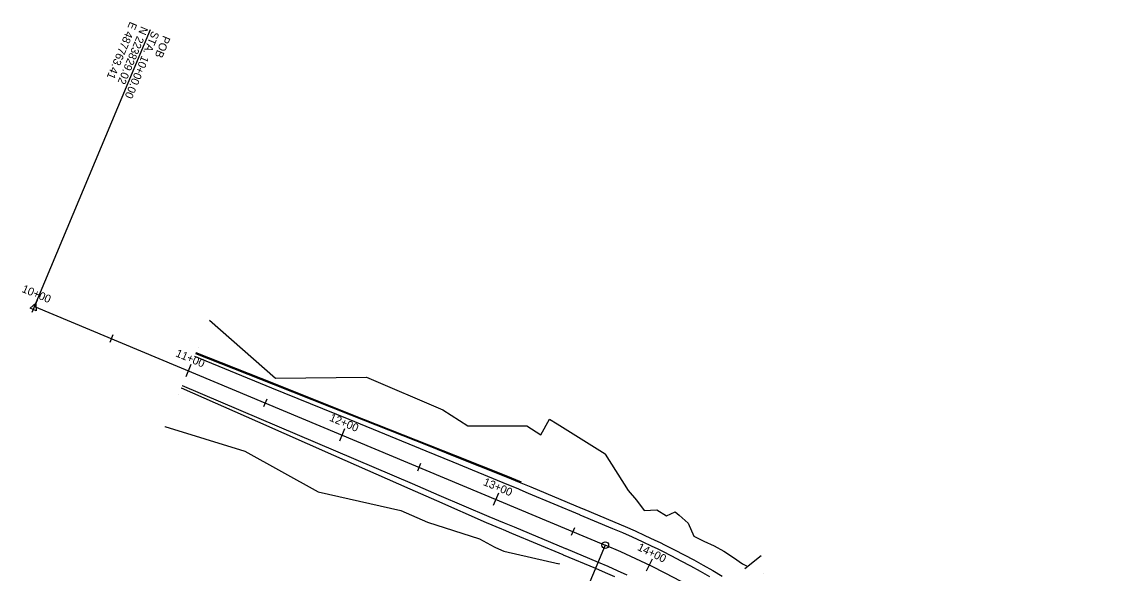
# Model space of a CAD drawing. Extents: x 487756 to 488722, y 222467 to 224000.
# Drawn here: x 487756 to 488413, y 223669 to 224000 of the extents above; entities that cross this region are included whole.
import ezdxf

# ---------------------------------------------------------------- set-up
doc = ezdxf.new("R2010")
doc.units = 0
for name, color, linetype in [('HM-SMOD-BRK LINE', 7, 'Continuous'), ('HR-FEAT-BCPC', 7, 'Continuous'), ('HR-FEAT-CUT', 7, 'Continuous'), ('HR-FEAT-EOR', 7, 'Continuous'), ('HR-FEAT-FILL', 7, 'Continuous'), ('HR-GMSC-HOR_VER ALN', 7, 'Continuous'), ('HR-GMSC-PCPT SYMB', 7, 'Continuous'), ('HR-GPLN-CL STA', 7, 'Continuous'), ('HR-GPLN-CL TICKS', 7, 'Continuous'), ('HR-GPLN-PCPT LDR', 7, 'Continuous'), ('HR-GPLN-PCPT TXT', 7, 'Continuous'), ('HR-GPLN-PI SYM', 7, 'Continuous'), ('SV_MISC_MISC_TOPO', 7, 'Continuous')]:
    doc.layers.add(name, color=color, linetype=linetype)

msp = doc.modelspace()

# ---------------------------------------------------------------- linework, layer by layer
at = {"layer": 'HM-SMOD-BRK LINE'}
for points in [[(487859.32, 223799.16), (487905.59, 223780.2), (487951.85, 223761.24), (487998.12, 223742.28), (488014.26, 223735.66), (488044.39, 223723.31), (488053.61, 223719.45), (488054.53, 223719.07), (488059.53, 223716.97), (488090.34, 223704.08), (488090.51, 223704.01), (488110.01, 223695.84), (488115.99, 223693.3), (488121.93, 223690.67), (488127.84, 223687.97), (488133.72, 223685.2), (488136.87, 223683.67), (488139.57, 223682.35), (488145.37, 223679.43), (488151.14, 223676.43), (488156.87, 223673.36), (488162.56, 223670.22), (488168.21, 223667)], [(487851.94, 223781.54), (487897.93, 223761.91), (487943.92, 223742.28), (487989.9, 223722.65), (488005.94, 223715.81), (488035.89, 223703.02), (488045.11, 223699.16), (488046.04, 223698.77), (488051.03, 223696.68), (488081.84, 223683.79), (488082.01, 223683.71), (488101.51, 223675.55), (488107.23, 223673.11), (488112.92, 223670.6), (488118.58, 223668.02)]]:
    msp.add_lwpolyline(points, dxfattribs=at)
at = {"layer": 'HR-FEAT-BCPC'}
msp.add_lwpolyline([(487860.2, 223801.27), (487906.69, 223782.84), (487953.18, 223764.41), (487999.67, 223745.97), (488015.88, 223739.55), (488046.16, 223727.54), (488055.38, 223723.68)], dxfattribs=at)
at = {"layer": 'HR-FEAT-CUT'}
msp.add_lwpolyline([(487868.36, 223820.76), (487908.02, 223786.02), (487962.45, 223786.56), (488008.4, 223766.85), (488023.34, 223757.35), (488058.62, 223757.31), (488067.17, 223751.84), (488072.27, 223761.43), (488076.9, 223758.46), (488105.58, 223740.49), (488105.69, 223740.27), (488119.55, 223718.64), (488124.43, 223712.77), (488129.07, 223706.58), (488136.66, 223706.96), (488142.41, 223703.3), (488147.68, 223705.81), (488150.13, 223703.67), (488155.38, 223699), (488158.86, 223691.07), (488164.93, 223688.17), (488170.98, 223685.25), (488176.93, 223682.11), (488182.56, 223678.43), (488188.03, 223674.5), (488190.48, 223673.35)], dxfattribs=at)
at = {"layer": 'HR-FEAT-EOR'}
for points in [[(487859.98, 223800.73), (487906.47, 223782.3), (487952.95, 223763.87), (487999.44, 223745.44), (488015.66, 223739.01), (488045.93, 223727), (488055.15, 223723.14), (488056.08, 223722.76), (488061.07, 223720.66), (488091.88, 223707.77), (488092.05, 223707.7), (488111.55, 223699.53), (488117.58, 223696.97), (488123.57, 223694.32), (488129.53, 223691.6), (488135.45, 223688.81), (488138.63, 223687.27), (488141.34, 223685.93), (488147.19, 223682.99), (488153.01, 223679.97), (488158.78, 223676.87), (488164.51, 223673.71), (488170.21, 223670.47), (488175.86, 223667.16)], [(487851.33, 223780.07), (487897.08, 223759.88), (487942.84, 223739.7), (487988.59, 223719.52), (488004.55, 223712.48), (488034.35, 223699.33), (488043.57, 223695.47), (488044.49, 223695.08), (488049.49, 223692.99), (488080.3, 223680.1), (488080.47, 223680.02), (488099.97, 223671.86), (488105.64, 223669.44), (488111.29, 223666.95)]]:
    msp.add_lwpolyline(points, dxfattribs=at)
at = {"layer": 'HR-FEAT-FILL'}
for points in [[(487841.6, 223756.84), (487889.64, 223742.12), (487933.64, 223717.74), (487983.19, 223706.6), (487999.1, 223699.46), (488030.24, 223689.53), (488039.07, 223684.72), (488039.97, 223684.29), (488044.96, 223682.17), (488078, 223674.62), (488078.31, 223674.87)], [(488189.49, 223671.75), (488199.14, 223679.55)]]:
    msp.add_lwpolyline(points, dxfattribs=at)
at = {"layer": 'HR-GMSC-HOR_VER ALN'}
msp.add_line((487763.41, 223829.02), (488105.76, 223685.7), dxfattribs=at)
msp.add_arc((487912.68, 223224.48), 500, 355.86194, 67.2843, dxfattribs=at)
at = {"layer": 'HR-GMSC-PCPT SYMB'}
msp.add_circle((488105.76, 223685.7), 2, dxfattribs=at)
at = {"layer": 'HR-GPLN-CL TICKS'}
for points in [[(487764.95, 223832.71), (487761.86, 223825.33)], [(487810.5, 223812.01), (487808.56, 223807.4)], [(487857.2, 223794.09), (487854.11, 223786.71)], [(487902.74, 223773.4), (487900.81, 223768.79)], [(487949.44, 223755.47), (487946.35, 223748.09)], [(487994.98, 223734.78), (487993.05, 223730.17)], [(488041.68, 223716.86), (488038.59, 223709.48)], [(488087.23, 223696.17), (488085.29, 223691.55)], [(488133.8, 223677.38), (488130.29, 223670.2)]]:
    msp.add_lwpolyline(points, dxfattribs=at)
at = {"layer": 'HR-GPLN-PCPT LDR'}
for points in [[(487763.41, 223829.02), (487832.92, 223995.05)], [(488105.76, 223685.7), (488036.25, 223519.66)]]:
    msp.add_lwpolyline(points, dxfattribs=at)
at = {"layer": 'HR-GPLN-PI SYM'}
msp.add_lwpolyline([(487764.18, 223830.86), (487764.48, 223826.4), (487760.79, 223827.94)], close=True, dxfattribs=at)
at = {"layer": 'SV_MISC_MISC_TOPO'}
for p, q in [((487868.36, 223820.76), (487868.36, 223820.76)), ((487868.36, 223820.76), (487868.36, 223820.76)), ((487861.52, 223804.42), (487861.52, 223804.42)), ((487859.32, 223799.16), (487859.32, 223799.16)), ((487859.98, 223800.73), (487859.98, 223800.73)), ((487859.98, 223800.73), (487859.98, 223800.73)), ((487860.11, 223801.05), (487860.11, 223801.05)), ((487860.2, 223801.27), (487860.2, 223801.27)), ((487855.65, 223790.4), (487855.65, 223790.4)), ((487908.02, 223786.02), (487908.02, 223786.02)), ((487962.45, 223786.56), (487962.45, 223786.56)), ((487851.33, 223780.07), (487851.33, 223780.07)), ((487851.94, 223781.54), (487851.94, 223781.54)), ((487849.78, 223776.38), (487849.78, 223776.38)), ((488008.4, 223766.85), (488008.4, 223766.85)), ((488072.27, 223761.43), (488072.27, 223761.43)), ((488076.9, 223758.46), (488076.9, 223758.46)), ((487841.6, 223756.84), (487841.6, 223756.84)), ((488023.34, 223757.35), (488023.34, 223757.35)), ((488058.62, 223757.31), (488058.62, 223757.31)), ((488067.17, 223751.84), (488067.17, 223751.84)), ((487889.64, 223742.12), (487889.64, 223742.12)), ((488105.58, 223740.49), (488105.58, 223740.49)), ((488105.69, 223740.27), (488105.69, 223740.27)), ((488119.55, 223718.64), (488119.55, 223718.64)), ((487933.64, 223717.74), (487933.64, 223717.74)), ((488124.43, 223712.77), (488124.43, 223712.77)), ((487983.19, 223706.6), (487983.19, 223706.6)), ((488129.07, 223706.58), (488129.07, 223706.58)), ((488136.66, 223706.96), (488136.66, 223706.96)), ((488147.68, 223705.81), (488147.68, 223705.81)), ((487999.1, 223699.46), (487999.1, 223699.46)), ((488142.41, 223703.3), (488142.41, 223703.3)), ((488150.13, 223703.67), (488150.13, 223703.67)), ((488155.38, 223699), (488155.38, 223699)), ((488030.24, 223689.53), (488030.24, 223689.53)), ((488158.86, 223691.07), (488158.86, 223691.07)), ((488164.93, 223688.17), (488164.93, 223688.17)), ((488170.98, 223685.25), (488170.98, 223685.25)), ((488039.07, 223684.72), (488039.07, 223684.72)), ((488039.97, 223684.29), (488039.97, 223684.29)), ((488044.96, 223682.17), (488044.96, 223682.17)), ((488176.93, 223682.11), (488176.93, 223682.11)), ((488199.14, 223679.55), (488199.14, 223679.55)), ((488078, 223674.62), (488078, 223674.62)), ((488078.31, 223674.87), (488078.31, 223674.87)), ((488182.56, 223678.43), (488182.56, 223678.43)), ((488188.03, 223674.5), (488188.03, 223674.5)), ((488190.48, 223673.35), (488190.48, 223673.35)), ((488200.45, 223668.99), (488200.45, 223668.99))]:
    msp.add_line(p, q, dxfattribs=at)

# ---------------------------------------------------------------- texts
at = {"layer": 'HR-GPLN-CL STA'}
for s, rotation, p in [('10+00', 337.2843, (487755.43, 223837.78)), ('11+00', 337.2843, (487847.67, 223799.16)), ('12+00', 337.2843, (487939.92, 223760.54)), ('13+00', 337.2843, (488032.16, 223721.93)), ('14+00', 333.97692, (488124.59, 223683))]:
    msp.add_text(s, height=4.8, rotation=rotation, dxfattribs=at).set_placement(p)
at = {"layer": 'HR-GPLN-PCPT TXT'}
for s, p in [('E 487763.41', (487820.74, 224000.15)), ('N 223829.02', (487827.38, 223997.37)), ('STA. 10+00.00', (487834.02, 223994.59)), ('POB ', (487840.67, 223991.81))]:
    msp.add_text(s, height=4.8, rotation=247.2843, dxfattribs=at).set_placement(p)

doc.saveas('drawing.dxf')
